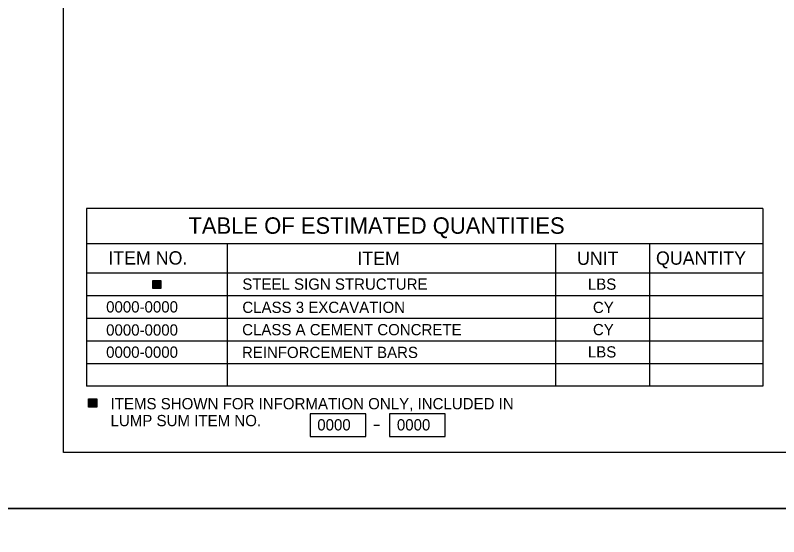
# Model space of a CAD drawing. Extents: x 3831399 to 3833095, y 499014 to 500202.
# Drawn here: x 3832267.3 to 3832471.3, y 499600.5 to 499739.8 of the extents above; entities that cross this region are included whole.
import ezdxf

# ---------------------------------------------------------------- set-up
doc = ezdxf.new("R2010")
doc.units = 0
for name, color, linetype in [('2', 7, 'Continuous'), ('DIM TXT', 7, 'Continuous'), ('PLT-BNDY', 7, 'Continuous')]:
    doc.layers.add(name, color=color, linetype=linetype)

msp = doc.modelspace()

# ---------------------------------------------------------------- linework, layer by layer
at = {"layer": '2'}
for p, q in [((3832280.16, 499623.03), (3832280.16, 500187.03)), ((3833066.16, 499623.03), (3832280.16, 499623.03))]:
    msp.add_line(p, q, dxfattribs=at)
at = {"layer": 'DIM TXT'}
for p, q in [((3832467.03, 499688.16), (3832286.28, 499688.16)), ((3832286.28, 499688.16), (3832286.28, 499640.7)), ((3832467.03, 499688.16), (3832467.03, 499640.7)), ((3832467.03, 499678.76), (3832286.28, 499678.76)), ((3832323.88, 499678.76), (3832323.88, 499640.7)), ((3832411.62, 499678.76), (3832411.62, 499640.7)), ((3832436.69, 499678.76), (3832436.69, 499640.7)), ((3832467.03, 499670.92), (3832286.28, 499670.93)), ((3832303.99, 499667.05), (3832305.95, 499669)), ((3832303.99, 499667.31), (3832305.68, 499669)), ((3832303.99, 499667.58), (3832305.42, 499669)), ((3832303.99, 499667.84), (3832305.15, 499669)), ((3832303.99, 499668.11), (3832304.89, 499669)), ((3832303.99, 499668.37), (3832304.62, 499669)), ((3832303.99, 499668.64), (3832304.36, 499669)), ((3832303.99, 499668.9), (3832304.09, 499669)), ((3832304.04, 499666.83), (3832306.17, 499668.95)), ((3832304.31, 499666.83), (3832306.17, 499668.69)), ((3832304.57, 499666.83), (3832306.17, 499668.42)), ((3832304.84, 499666.83), (3832306.17, 499668.16)), ((3832305.1, 499666.83), (3832306.17, 499667.89)), ((3832305.37, 499666.83), (3832306.17, 499667.63)), ((3832305.63, 499666.83), (3832306.17, 499667.36)), ((3832305.9, 499666.83), (3832306.17, 499667.1)), ((3832467.03, 499664.88), (3832286.28, 499664.88)), ((3832306.16, 499666.83), (3832306.17, 499666.83)), ((3832467.03, 499658.83), (3832286.28, 499658.84)), ((3832467.03, 499652.79), (3832286.28, 499652.79)), ((3832467.03, 499646.74), (3832286.28, 499646.75)), ((3832461.76, 499640.7), (3832286.28, 499640.7)), ((3832467.03, 499640.7), (3832286.28, 499640.7)), ((3832286.86, 499635.37), (3832288.81, 499637.32)), ((3832286.86, 499635.63), (3832288.55, 499637.32)), ((3832286.86, 499635.9), (3832288.28, 499637.32)), ((3832286.86, 499636.16), (3832288.02, 499637.32)), ((3832286.86, 499636.43), (3832287.75, 499637.32)), ((3832286.86, 499636.69), (3832287.49, 499637.32)), ((3832286.86, 499636.96), (3832287.22, 499637.32)), ((3832286.86, 499637.22), (3832286.96, 499637.32)), ((3832286.91, 499635.15), (3832289.03, 499637.27)), ((3832287.17, 499635.15), (3832289.03, 499637.01)), ((3832287.44, 499635.15), (3832289.03, 499636.74)), ((3832287.7, 499635.15), (3832289.03, 499636.48)), ((3832287.97, 499635.15), (3832289.03, 499636.21)), ((3832288.23, 499635.15), (3832289.03, 499635.95)), ((3832288.5, 499635.15), (3832289.03, 499635.68)), ((3832288.76, 499635.15), (3832289.03, 499635.42)), ((3832289.03, 499635.15), (3832289.03, 499635.15)), ((3832363.12, 499630.3), (3832364.58, 499630.3))]:
    msp.add_line(p, q, dxfattribs=at)
for points in [[(3832303.99, 499669), (3832306.17, 499669), (3832306.17, 499666.83), (3832303.99, 499666.83)], [(3832286.86, 499637.32), (3832289.03, 499637.32), (3832289.03, 499635.15), (3832286.86, 499635.15)], [(3832346.04, 499627.34), (3832360.9, 499627.34), (3832360.9, 499633.33), (3832346.04, 499633.33)], [(3832367.3, 499627.34), (3832382.15, 499627.34), (3832382.15, 499633.33), (3832367.3, 499633.33)]]:
    msp.add_lwpolyline(points, close=True, dxfattribs=at)
at = {"layer": 'PLT-BNDY'}
for points in [[(3832240.16, 500202.03), (3833081.16, 500202.03), (3833081.16, 499608.03), (3832240.16, 499608.03)], [(3832240.16, 499608.03), (3833081.16, 499608.03), (3833081.16, 499014.03), (3832240.16, 499014.03)]]:
    msp.add_lwpolyline(points, close=True, dxfattribs=at)

# ---------------------------------------------------------------- texts
at = {"layer": 'DIM TXT'}
for s, height, p in [('TABLE OF ESTIMATED QUANTITIES', 4.3922, (3832313.55, 499681.44)), ('ITEM NO.', 3.557, (3832292.12, 499673.22)), ('ITEM', 3.557, (3832358.67, 499673.1)), ('UNIT', 3.557, (3832417.37, 499673.13)), ('QUANTITY', 3.557, (3832438.46, 499673.17)), ('STEEL SIGN STRUCTURE', 2.9999, (3832327.94, 499666.5)), ('LBS', 3, (3832420.27, 499666.49)), ('0000-0000', 3, (3832291.56, 499660.42)), ('CLASS 3 EXCAVATION', 2.9999, (3832327.95, 499660.3)), ('CY', 3, (3832421.62, 499660.28)), ('0000-0000', 3, (3832291.56, 499654.25)), ('CLASS A CEMENT CONCRETE', 2.9999, (3832327.9, 499654.33)), ('CY', 3, (3832421.62, 499654.35)), ('0000-0000', 3, (3832291.56, 499648.33)), ('REINFORCEMENT BARS', 2.9999, (3832327.84, 499648.26)), ('LBS', 3, (3832420.27, 499648.4)), ('ITEMS SHOWN FOR INFORMATION ONLY, INCLUDED IN', 3.0083, (3832292.73, 499634.56)), ('LUMP SUM ITEM NO. ', 3.0083, (3832292.73, 499630.05)), ('0000', 3, (3832347.97, 499628.92)), ('0000', 3, (3832369.24, 499628.92))]:
    msp.add_text(s, height=height, dxfattribs=at).set_placement(p)

doc.saveas('drawing.dxf')
